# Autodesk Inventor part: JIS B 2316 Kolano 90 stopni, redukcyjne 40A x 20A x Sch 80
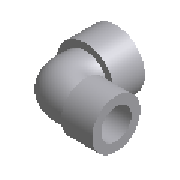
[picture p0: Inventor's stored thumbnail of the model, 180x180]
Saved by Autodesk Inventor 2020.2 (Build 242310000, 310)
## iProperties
Manager: www.cadconsulting.pl
Company: Fabian Stasiak CAD Consulting
Created: 2014-02
Part Number: JIS B 2316 Kolano 90 stopni, redukcyjne 40A x 20A x Sch 80
Material: Stal
Description: Kolanko redukcyjne
Document SubType Name: Modeling
Standard: JIS B 2316
Designer: F.Stasiak
Standards Organization: JIS
Language: pl-PL
Size Designation: 40A x 20A x Sch 80
Categories: <MemberInstance><Categories><Category DisplayName="Rury cienko- i grubościenne" InternalName="4347fa0f-2144-441d-94cd-e3e15c92b736" Mnemonic="TUBEANDPIPE"><Cate
Density: 1 g/cm^3
Appearance: Płyta
Catalog Web Link: www.expertbooks.pl
NAME: PIPING: JIS B 2316 90 Deg Reduced Elbow
DATA: <meta><inlinegroups number="0" deflen="0"></inlinegroups><connections number="2"></connections><angles><a>1.5707963267949</a></angles></meta>
Author: F.Stasiak
Subject: Zbiór ćwiczeń. Autodesk Inventor 2020. Kurs Professional
IsCustomPart: 0
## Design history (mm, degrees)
sketch "Sketch1"
  geometry: L1 (0, 0)-(0, 15.5); L2 (0, 0)-(24.55, 0); L3 (30.15, 0)-(30.15, 15.5); L4 (30.15, 15.5)-(20.6, 15.5); L5 (24.55, 0)-(24.55, 12.7); L6 (24.55, 12.7)-(20.6, 12.7); L7 (20.6, 12.7)-(20.6, 15.5); L8 (24.55, 0)-(30.15, 0)
  constraints: 16 end point, 3 perpendicular, 1 collinear, 1 parallel, 1 point on line, 1 vertical
  dimensions: "d0" = 41.2 diameter of L7 L1 (= D1); "d1" = 49.1 diameter of L5 L1 (= S1); "d2" = 5.6 distance between parallel lines of L5 L3 (= T); "d3" = 12.7 distance between parallel lines of L8 L6 (= C11); "d12" = 2.8 distance between parallel lines of L6 L4 (= 0.5 x T)
revolve "Revolve1" sketch "Sketch1" stored, may be unused: angle "d8" = 90 deg
sketch "Sketch2"
  geometry: L1 (-29, 44.5)-(-44.5, 44.5); L2 (-44.5, 44.5)-(-44.5, 30.9); L3 (-44.5, 25.3)-(-29, 25.3); L4 (-29, 25.3)-(-29, 33.8); L5 (-29, 33.8)-(-31.8, 33.8); L6 (-31.8, 33.8)-(-31.8, 30.9); L7 (-31.8, 30.9)-(-44.5, 30.9); L8 (-44.5, 30.9)-(-44.5, 25.3); L9 (0, 0)-(0, 15.5) reference; L10 (0, 0)-(24.55, 0) reference; L11 (-29, 44.5)-(0, 44.5); L12 (0, 44.5)-(0, 15.5); L13 (-20.6, 12.7)-(20.6, 12.7) reference
  constraints: 20 end point, 4 perpendicular, 3 collinear, 3 parallel, 1 point on line
  dimensions: "d4" = 21.4 diameter of L5 L1 (= D2); "d5" = 27.2 diameter of L7 L1 (= S2); "d6" = 5.6 distance between parallel lines of L3 L7 (= T); "d7" = 12.7 distance between parallel lines of L8 L6 (= C12); "d9" = 31.8 distance from line of L11.end L6 (= G); "d10" = 31.8 distance from line of L13 L11.end (= G); "d13" = 2.8 distance between parallel lines of L6 L4 (= 0.5 x T)
revolve "Revolve2" sketch "Sketch2" stored, may be unused: angle "d25" = 90 deg
sketch "Sketch3"
  geometry: L1 (-29, 44.5)-(0, 44.5); L2 (0, 44.5)-(0, 15.5); L3 (-29, 55.2)-(-29, 33.8) reference; L4 (-20.6, 15.5)-(20.6, 15.5) reference; L5 (0, 44.5)-(-29, 20.166)
  constraints: 6 end point, 2 midpoint, 2 perpendicular, 1 point on line
  dimensions: "d14" = 50 deg angle of L5 L2
sketch "Sketch4"
  geometry: C1 r 20.6 at (0, 0) reference; C2 r 20.6 at (0, 0); C3 r 26.2 at (0, 0)
  constraints: 3 concentric, 2 centre point, 2 coincident
  dimensions: "d11" = 52.4 diameter of C3 (= D1 + 2 x T)
sketch "Sketch5"
  geometry: C1 r 10.7 at (0, 0) reference; C2 r 10.7 at (0, 0); C3 r 16.3 at (0, 0); 3 further points
  constraints: 2 centre point, 2 coincident, 2 concentric, 2 other
  dimensions: "d15" = 32.6 diameter of C3 (= D2 + 2 x T)
workplane "Work Plane1"
sketch "Sketch6" dims "d18" = 48.76 (= 0.6 x D1 + 0.6 x D2 + 2 x T)
  geometry: L1 (8.24, 0)-(32.62, 0); C1 r 18.78 at (8.24, 0); 2 further points
  constraints: 2 coincident, 2 end point, 1 centre point, 1 horizontal, 1 horizontal alignment, 1 point on line, 3 other
  dimensions: "d17" = 37.56 diameter of C1 (= 0.6 x D2 + 0.6 x D1); "d32" = 8.24 distance of C1.centre point (0, 0) (= 0.2 x D1)
loft "Loft1" dims "d19" = 0, "d20" = 90 deg, "d21" = 0, "d22" = 90 deg, "d23" = 0, "d24" = 90 deg
loft "Loft2" dims "d26" = 0, "d27" = 90 deg, "d28" = 0, "d29" = 90 deg, "d30" = 0, "d31" = 90 deg
workaxis "Work Axis1"
workpoint "Work Point1"
workpoint "Work Point2"
workaxis "Work Axis2"
workpoint "Work Point3"
workpoint "Work Point4"
body "Solid1"
other parameters: "S1" = 49.1 [user parameter; used in 1 equation term], "D1" = 41.2 [user parameter; used in 5 equation terms], "T" = 5.6 [user parameter; used in 7 equation terms], "C11" = 12.7 [user parameter; used in 1 equation term], "G" = 31.8 [user parameter; used in 2 equation terms], "S2" = 27.2 [user parameter; used in 1 equation term], "D2" = 21.4 [user parameter; used in 4 equation terms], "C12" = 12.7 [user parameter; used in 1 equation term], "d16" = 90 deg, "Size_Designation" = 12.345 [user parameter]
